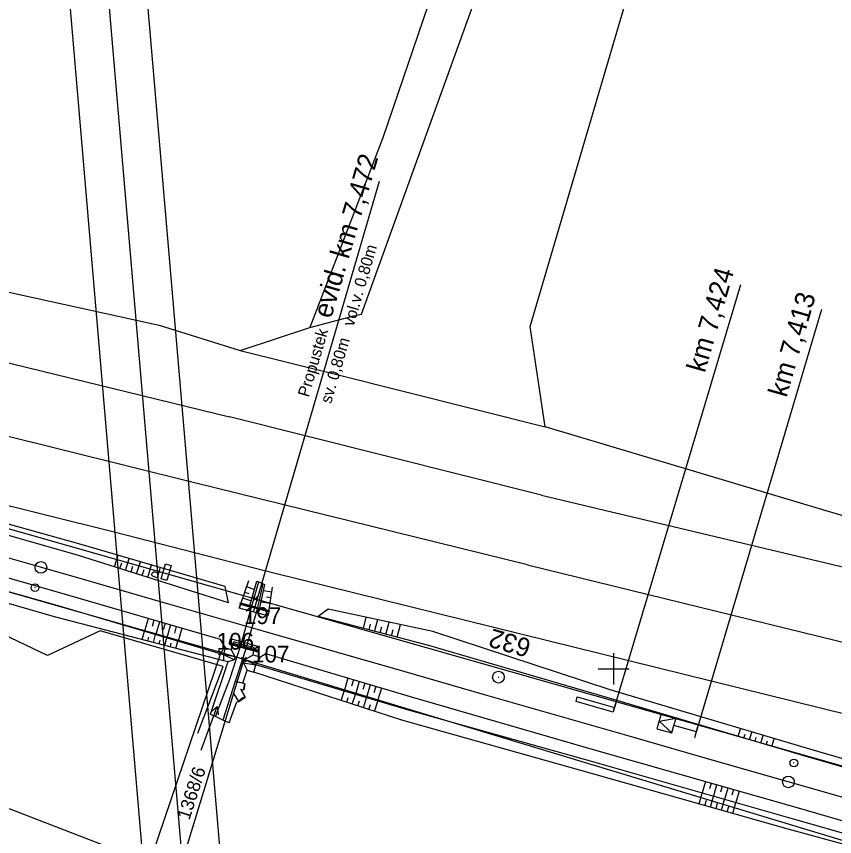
# Model space of a CAD drawing. Extents: x -779302 to -774398, y -1144902 to -1142831.
# Drawn here: x -777576.9 to -777471.5, y -1143721.6 to -1143615.9 of the extents above; entities that cross this region are included whole.
import ezdxf

# ---------------------------------------------------------------- set-up
doc = ezdxf.new("R2010")
doc.units = 0
for name, color, linetype in [('hektosit - Vrstva 5', 7, 'Continuous'), ('Hranice parcel', 7, 'Continuous'), ('legenda I_5_2 - Vrstva 53', 7, 'Continuous'), ('Parcelní čísla', 7, 'Continuous'), ('SŽDC', 7, 'Continuous'), ('Vnitřní kresba', 7, 'Continuous'), ('Vrstva 1', 7, 'Continuous'), ('zjednodus_g_situ-seda - Vrstva 1', 7, 'Continuous'), ('zjednodus_g_situ-seda - Vrstva 17', 7, 'Continuous'), ('zjednodus_g_situ-seda - Vrstva 19', 7, 'Continuous'), ('zjednodus_g_situ-seda - Vrstva 33', 7, 'Continuous'), ('zjednodus_g_situ-seda - Vrstva 48', 7, 'Continuous'), ('zjednodus_g_situ-seda - Vrstva 49', 7, 'Continuous'), ('zjednodus_g_situ-seda - Vrstva 63', 7, 'Continuous'), ('zjednodus_g_situ-seda - Vrstva 7', 7, 'Continuous'), ('zjednodus_g_situ-seda - Vrstva 8', 7, 'Continuous'), ('zjednodus_g_situ-seda - Vrstva 9', 7, 'Continuous'), ('Značky kultur', 7, 'Continuous')]:
    doc.layers.add(name, color=color, linetype=linetype)

msp = doc.modelspace()

# ---------------------------------------------------------------- linework, layer by layer
at = {"layer": 'hektosit - Vrstva 5'}
for p, q in [((-777500, -1143698), (-777500, -1143702)), ((-777502, -1143700), (-777498, -1143700))]:
    msp.add_line(p, q, dxfattribs=at)
at = {"layer": 'Hranice parcel'}
for p, q in [((-777548.1, -1143658.97), (-777539.12, -1143656)), ((-777550.6, -1143697.9), (-777622.38, -1143677.44)), ((-777550.6, -1143697.9), (-777559.79, -1143725)), ((-777547.63, -1143698.79), (-777556.08, -1143726.43)), ((-777547.63, -1143698.79), (-777550.6, -1143697.9))]:
    msp.add_line(p, q, dxfattribs=at)
for points in [[(-777508.79, -1143668.8), (-777510.73, -1143655.88), (-777497.53, -1143610.93), (-777481.94, -1143562.57), (-777470.6, -1143527.36), (-777466.94, -1143516.02), (-777464.9, -1143509.68)], [(-777496.86, -1143535.74), (-777517.68, -1143596.22), (-777520.04, -1143603.06), (-777529.74, -1143631.58), (-777539.12, -1143656)], [(-777539.12, -1143656), (-777533.45, -1143654.53), (-777532.48, -1143654.28), (-777515.5, -1143607.29), (-777513.98, -1143602.78), (-777492.04, -1143537.65)], [(-778102.74, -1143613.61), (-778067.87, -1143604.7), (-778036.9, -1143597.86), (-777971.64, -1143592.01), (-777964.3, -1143591.17), (-777890.59, -1143590.67), (-777860.75, -1143594.87), (-777857.58, -1143595.32), (-777803.43, -1143602.93), (-777799.69, -1143603.46), (-777791.04, -1143604.67), (-777558.56, -1143655.7), (-777548.1, -1143658.97)], [(-777375.98, -1143729.1), (-777462.56, -1143707.72), (-777543.96, -1143687.61), (-777544.8, -1143687.4), (-777564.35, -1143682.38), (-777643.12, -1143662.79), (-777672.41, -1143655.46), (-777784.28, -1143627.47), (-777786.92, -1143627.45)], [(-777548.1, -1143658.97), (-777536, -1143661.99), (-777508.79, -1143668.8)], [(-777773.53, -1143661.8), (-777723.87, -1143663.43), (-777711.36, -1143665.84), (-777650.39, -1143687.95), (-777582.96, -1143716.06), (-777559.79, -1143725)], [(-777371.14, -1143700.16), (-777375.2, -1143699.98), (-777393.58, -1143699.19), (-777466.8, -1143681.38), (-777472.61, -1143679.64), (-777508.79, -1143668.8)], [(-777600.4, -1143675.56), (-777546.18, -1143690.99), (-777447.49, -1143719.07), (-777442.54, -1143720.48)], [(-777358.14, -1143760.61), (-777362.08, -1143759.74), (-777364.95, -1143754.01), (-777547.63, -1143698.79)]]:
    msp.add_lwpolyline(points, dxfattribs=at)
at = {"layer": 'legenda I_5_2 - Vrstva 53'}
for points in [[(-777916.16, -1143663.29), (-777860.31, -1143656.58), (-777817.61, -1143650.87), (-777782.23, -1143650.25), (-777777.65, -1143650.04), (-777771.99, -1143649.79), (-777747.07, -1143649.03), (-777716.22, -1143651.23), (-777687.78, -1143654.61), (-777659.91, -1143659.97), (-777643.37, -1143663.67), (-777619.92, -1143670.03), (-777600.4, -1143675.56), (-777546.18, -1143690.99), (-777447.49, -1143719.07), (-777442.54, -1143720.48), (-777400.53, -1143733.41)], [(-777340.59, -1143770.61), (-777348.72, -1143768.82), (-777354.56, -1143760.13), (-777358.14, -1143760.61), (-777362.08, -1143759.74), (-777364.95, -1143754.01), (-777547.63, -1143698.79), (-777550.6, -1143697.9), (-777622.38, -1143677.44), (-777645.06, -1143671.66), (-777661.41, -1143667.34), (-777716.9, -1143658.83), (-777747.1, -1143656.66), (-777769.78, -1143657.38), (-777774.83, -1143658.21), (-777780.87, -1143658.4), (-777816.72, -1143661.12), (-777859.44, -1143665.66), (-777917.11, -1143671.65)]]:
    msp.add_lwpolyline(points, dxfattribs=at)
at = {"layer": 'SŽDC'}
for p, q in [((-777545.98, -1143691.19), (-777546.48, -1143690.69)), ((-777545.98, -1143690.79), (-777546.48, -1143691.29)), ((-777546.38, -1143691.19), (-777545.88, -1143690.69)), ((-777546.38, -1143690.79), (-777545.88, -1143691.29)), ((-777546.18, -1143690.99), (-777546.18, -1143690.99)), ((-777550.4, -1143698.1), (-777550.9, -1143697.6)), ((-777550.4, -1143697.7), (-777550.9, -1143698.2)), ((-777550.8, -1143698.1), (-777550.3, -1143697.6)), ((-777550.8, -1143697.7), (-777550.3, -1143698.2)), ((-777550.6, -1143697.9), (-777550.6, -1143697.9)), ((-777547.43, -1143698.99), (-777547.93, -1143698.49)), ((-777547.43, -1143698.59), (-777547.93, -1143699.09)), ((-777547.83, -1143698.99), (-777547.33, -1143698.49)), ((-777547.83, -1143698.59), (-777547.33, -1143699.09)), ((-777547.63, -1143698.79), (-777547.63, -1143698.79))]:
    msp.add_line(p, q, dxfattribs=at)
for points in [[(-777916.16, -1143663.29), (-777860.31, -1143656.58), (-777817.61, -1143650.87), (-777782.23, -1143650.25), (-777777.65, -1143650.04), (-777771.99, -1143649.79), (-777747.07, -1143649.03), (-777716.22, -1143651.23), (-777687.78, -1143654.61), (-777659.91, -1143659.97), (-777643.37, -1143663.67), (-777619.92, -1143670.03), (-777600.4, -1143675.56), (-777546.18, -1143690.99), (-777447.49, -1143719.07), (-777442.54, -1143720.48), (-777400.53, -1143733.41)], [(-777340.59, -1143770.61), (-777348.72, -1143768.82), (-777354.56, -1143760.13), (-777358.14, -1143760.61), (-777362.08, -1143759.74), (-777364.95, -1143754.01), (-777547.63, -1143698.79), (-777550.6, -1143697.9), (-777622.38, -1143677.44), (-777645.06, -1143671.66), (-777661.41, -1143667.34), (-777716.9, -1143658.83), (-777747.1, -1143656.66), (-777769.78, -1143657.38), (-777774.83, -1143658.21), (-777780.87, -1143658.4), (-777816.72, -1143661.12), (-777859.44, -1143665.66), (-777917.11, -1143671.65)]]:
    msp.add_lwpolyline(points, dxfattribs=at)
at = {"layer": 'Vnitřní kresba'}
for p, q in [((-777664.65, -1143639.46), (-777549.5, -1143667.53)), ((-777554.18, -1143676), (-777668.6, -1143647.45)), ((-777509.28, -1143677.62), (-777549.5, -1143667.53)), ((-777511.09, -1143686.61), (-777554.18, -1143676)), ((-777509.28, -1143677.62), (-777391.49, -1143705.71)), ((-777511.09, -1143686.61), (-777400.48, -1143713.69))]:
    msp.add_line(p, q, dxfattribs=at)
at = {"layer": 'Vrstva 1'}
for points in [[(-777571, -1143485.76), (-778617.18, -1143575.21), (-778591.88, -1143871.12), (-777545.7, -1143781.67)], [(-777551.11, -1143777.12), (-778587.32, -1143865.71), (-778611.77, -1143579.77), (-777575.56, -1143491.17)], [(-777580.11, -1143496.57), (-778407.09, -1143567.28), (-778383.5, -1143843.27), (-777556.51, -1143772.57)]]:
    msp.add_lwpolyline(points, close=True, dxfattribs=at)
at = {"layer": 'zjednodus_g_situ-seda - Vrstva 1'}
msp.add_lwpolyline([(-777408.97, -1143734.24), (-777420.06, -1143731.06), (-777430.69, -1143728), (-777441.98, -1143724.76), (-777451.96, -1143721.89), (-777462.83, -1143718.78), (-777473.72, -1143715.65), (-777477.48, -1143714.57), (-777487.28, -1143711.76), (-777497.37, -1143708.86), (-777507.6, -1143705.92), (-777516.61, -1143703.33), (-777526.83, -1143700.4), (-777537.5, -1143697.33), (-777545.14, -1143695.15), (-777548.77, -1143694.1), (-777557.76, -1143691.53), (-777568.3, -1143688.5), (-777573.86, -1143686.91), (-777584.11, -1143683.97)], dxfattribs=at)
at = {"layer": 'zjednodus_g_situ-seda - Vrstva 17'}
for p, q in [((-777544.39, -1143692.58), (-777548.07, -1143691.58)), ((-777545.82, -1143697.74), (-777549.51, -1143696.75))]:
    msp.add_line(p, q, dxfattribs=at)
msp.add_lwpolyline([(-777553.57, -1143708.27), (-777550.29, -1143699.69), (-777566.17, -1143695.1), (-777572.92, -1143698.27), (-777586.19, -1143691.95), (-777600.66, -1143686.16), (-777614.28, -1143682.28), (-777621.4, -1143682.89)], dxfattribs=at)
at = {"layer": 'zjednodus_g_situ-seda - Vrstva 19'}
for p, q in [((-777546.39, -1143692.68), (-777530.17, -1143637.17)), ((-777546.89, -1143691.99), (-777545.95, -1143688.7)), ((-777546.66, -1143692.05), (-777545.71, -1143688.79)), ((-777545.88, -1143692.25), (-777545.16, -1143689.04)), ((-777545.6, -1143692.33), (-777544.92, -1143689.12)), ((-777548.05, -1143691.51), (-777544.37, -1143692.52)), ((-777544.41, -1143692.65), (-777548.1, -1143691.67)), ((-777548, -1143696.82), (-777546.66, -1143692.05)), ((-777548, -1143696.82), (-777546.65, -1143692.05)), ((-777547.26, -1143697.02), (-777545.88, -1143692.26)), ((-777547.25, -1143697.02), (-777545.88, -1143692.25)), ((-777545.78, -1143697.62), (-777549.48, -1143696.61)), ((-777545.65, -1143697.15), (-777549.36, -1143696.15)), ((-777549.28, -1143697.49), (-777548.99, -1143696.75)), ((-777548.99, -1143696.75), (-777546.35, -1143697.47)), ((-777548, -1143696.82), (-777548.94, -1143696.52)), ((-777549.5, -1143696.82), (-777545.84, -1143697.81)), ((-777548.76, -1143698.45), (-777549.28, -1143697.49)), ((-777546.3, -1143697.27), (-777547.26, -1143697.02)), ((-777546.44, -1143698.25), (-777546.35, -1143697.47)), ((-777546.35, -1143697.47), (-777546.3, -1143697.27)), ((-777545.79, -1143697.62), (-777546.35, -1143697.47)), ((-777548.76, -1143698.45), (-777550.2, -1143698.19)), ((-777548.89, -1143698.83), (-777550.2, -1143698.19)), ((-777548.89, -1143698.83), (-777549.7, -1143699.1)), ((-777548.76, -1143698.45), (-777548.89, -1143698.83)), ((-777547.5, -1143698.79), (-777547.7, -1143699.24)), ((-777546.44, -1143698.25), (-777547.5, -1143698.79)), ((-777547.5, -1143698.79), (-777546.08, -1143699.47)), ((-777545.51, -1143698.5), (-777546.44, -1143698.25)), ((-777549.7, -1143699.1), (-777551.99, -1143705.87)), ((-777547.7, -1143699.24), (-777547.22, -1143700.18)), ((-777547.7, -1143699.24), (-777546.08, -1143699.47)), ((-777547.49, -1143701.91), (-777548.76, -1143701.61)), ((-777547.76, -1143701.86), (-777548.76, -1143701.61)), ((-777547.49, -1143701.91), (-777547.76, -1143701.86)), ((-777547.49, -1143701.91), (-777547.64, -1143702.7)), ((-777547.63, -1143702.7), (-777547.49, -1143701.91)), ((-777547.49, -1143701.91), (-777547.49, -1143701.91)), ((-777548.29, -1143704.2), (-777548.95, -1143703.09)), ((-777548.28, -1143704.2), (-777548.95, -1143703.09)), ((-777547.47, -1143703.65), (-777548.03, -1143702.62)), ((-777548.03, -1143702.62), (-777547.64, -1143702.7)), ((-777548.03, -1143702.62), (-777547.63, -1143702.7)), ((-777547.64, -1143702.7), (-777547.63, -1143702.7)), ((-777548.52, -1143704.23), (-777548.29, -1143704.2)), ((-777549.51, -1143706.95), (-777548.52, -1143704.23)), ((-777551.27, -1143706.14), (-777551.99, -1143705.87)), ((-777549.51, -1143706.95), (-777550.36, -1143706.63))]:
    msp.add_line(p, q, dxfattribs=at)
for points in [[(-777545.95, -1143688.7), (-777545.71, -1143688.79), (-777545.16, -1143689.04), (-777544.92, -1143689.12)], [(-777548.04, -1143691.52), (-777548.05, -1143691.51), (-777548.1, -1143691.67), (-777548.09, -1143691.67), (-777548.22, -1143692.18)], [(-777548.22, -1143692.18), (-777548.04, -1143691.52)], [(-777544.56, -1143693.18), (-777544.37, -1143692.52), (-777548.04, -1143691.52)], [(-777544.56, -1143693.18), (-777548.22, -1143692.18)], [(-777544.41, -1143692.65), (-777545.6, -1143692.33), (-777545.88, -1143692.25), (-777545.88, -1143692.26), (-777546.65, -1143692.05), (-777546.66, -1143692.05), (-777546.89, -1143691.99), (-777548.09, -1143691.67)], [(-777544.37, -1143692.52), (-777544.37, -1143692.52), (-777544.41, -1143692.65), (-777544.41, -1143692.65), (-777544.56, -1143693.18)], [(-777545.65, -1143697.15), (-777545.83, -1143697.81), (-777549.5, -1143696.82), (-777549.36, -1143696.15)], [(-777549.5, -1143696.82), (-777549.5, -1143696.82), (-777549.48, -1143696.61), (-777549.47, -1143696.61), (-777549.36, -1143696.15)], [(-777549.47, -1143696.61), (-777548.99, -1143696.75), (-777548.94, -1143696.52)], [(-777546.3, -1143697.27), (-777547.25, -1143697.02), (-777547.26, -1143697.02), (-777548, -1143696.82), (-777548, -1143696.82), (-777548.94, -1143696.52)], [(-777550.36, -1143706.63), (-777551.27, -1143706.14), (-777549.43, -1143701.35), (-777548, -1143696.82)], [(-777547.25, -1143697.02), (-777548.76, -1143701.61), (-777550.36, -1143706.63)], [(-777549.7, -1143699.1), (-777550.2, -1143698.98), (-777550.2, -1143698.19), (-777550.01, -1143697.31), (-777549.28, -1143697.49)], [(-777545.83, -1143697.81), (-777545.84, -1143697.81), (-777545.78, -1143697.62), (-777545.79, -1143697.62), (-777545.65, -1143697.15)], [(-777546.36, -1143700.42), (-777546.08, -1143699.47), (-777545.51, -1143698.5)], [(-777547.76, -1143701.86), (-777547.22, -1143700.18), (-777546.36, -1143700.42)], [(-777548.03, -1143702.62), (-777548.03, -1143702.62), (-777547.47, -1143703.65)], [(-777548.29, -1143704.2), (-777548.28, -1143704.2), (-777547.47, -1143703.65), (-777547.47, -1143703.65), (-777548.29, -1143704.2)]]:
    msp.add_lwpolyline(points, dxfattribs=at)
for centre, major_axis, ratio, start_param, end_param in [((-777547.59, -1143702.31), (-0.048, -0.25), 0.006452, 6.263484, 10.990254), ((-777547.59, -1143702.31), (-0.048, -0.25), 0.006452, 4.707068, 7.833837), ((-777547.97, -1143703.87), (0.234, 0.197), 0.005166, 1.392493, 4.908137), ((-777547.97, -1143703.87), (0.234, 0.197), 0.005166, 4.908137, 9.235346)]:
    msp.add_ellipse(centre, major_axis=major_axis, ratio=ratio, start_param=start_param, end_param=end_param, dxfattribs=at)
at = {"layer": 'zjednodus_g_situ-seda - Vrstva 33'}
msp.add_line((-777544.3, -1143692.6), (-777548.16, -1143691.52), dxfattribs=at)
msp.add_lwpolyline([(-777558.45, -1143687.05), (-777558.79, -1143688.26), (-777559.29, -1143688.11), (-777559.43, -1143688.02), (-777559.48, -1143687.79), (-777559.45, -1143687.69), (-777559.29, -1143687.52), (-777559.12, -1143687.52), (-777558.62, -1143687.66)], dxfattribs=at)
msp.add_lwpolyline([(-777557.57, -1143688.6), (-777558.29, -1143688.4), (-777557.73, -1143686.46), (-777557.02, -1143686.67)], close=True, dxfattribs=at)
at = {"layer": 'zjednodus_g_situ-seda - Vrstva 48'}
for p, q in [((-777564.32, -1143686.86), (-777563.85, -1143685.36)), ((-777562.89, -1143687.31), (-777562.41, -1143685.78)), ((-777561.46, -1143687.76), (-777560.97, -1143686.2)), ((-777563.6, -1143687.08), (-777563.37, -1143686.33)), ((-777562.17, -1143687.53), (-777561.93, -1143686.76)), ((-777560.74, -1143687.98), (-777560.49, -1143687.2)), ((-777560.03, -1143688.21), (-777559.53, -1143686.62)), ((-777547.3, -1143689.41), (-777546.26, -1143689.78)), ((-777547.55, -1143690.12), (-777547.01, -1143690.31)), ((-777544.05, -1143690.11), (-777545.1, -1143689.96)), ((-777547.8, -1143690.83), (-777546.67, -1143691.22)), ((-777544.26, -1143691.59), (-777545.41, -1143691.43)), ((-777544.16, -1143690.85), (-777544.7, -1143690.77)), ((-777559.95, -1143693.51), (-777560.43, -1143695.16)), ((-777532.24, -1143694.79), (-777531.86, -1143693.34)), ((-777559.23, -1143693.72), (-777559.47, -1143694.55)), ((-777558.51, -1143693.93), (-777558.99, -1143695.59)), ((-777557.79, -1143694.14), (-777558.03, -1143694.97)), ((-777557.07, -1143694.35), (-777557.56, -1143696.01)), ((-777556.35, -1143694.56), (-777556.59, -1143695.4)), ((-777531.51, -1143694.98), (-777531.32, -1143694.24)), ((-777530.79, -1143695.18), (-777530.39, -1143693.66)), ((-777530.06, -1143695.37), (-777529.86, -1143694.59)), ((-777529.34, -1143695.56), (-777528.92, -1143693.97)), ((-777527.89, -1143695.94), (-777527.45, -1143694.29)), ((-777560.74, -1143696.24), (-777560.46, -1143695.16)), ((-777559.29, -1143696.62), (-777559.02, -1143695.58)), ((-777555.63, -1143694.78), (-777556.12, -1143696.44)), ((-777528.61, -1143695.75), (-777528.4, -1143694.94)), ((-777560.02, -1143696.43), (-777559.88, -1143695.9)), ((-777558.56, -1143696.8), (-777558.43, -1143696.3)), ((-777557.84, -1143696.99), (-777557.58, -1143696.01)), ((-777557.11, -1143697.18), (-777556.99, -1143696.7)), ((-777556.39, -1143697.37), (-777556.14, -1143696.43)), ((-777534.22, -1143701.21), (-777534.71, -1143702.86)), ((-777533.5, -1143701.43), (-777533.75, -1143702.25)), ((-777532.78, -1143701.64), (-777533.27, -1143703.29)), ((-777532.06, -1143701.86), (-777532.31, -1143702.68)), ((-777531.35, -1143702.07), (-777531.84, -1143703.71)), ((-777535.1, -1143704.08), (-777534.7, -1143702.86)), ((-777530.63, -1143702.28), (-777530.87, -1143703.11)), ((-777529.91, -1143702.5), (-777530.4, -1143704.14)), ((-777534.38, -1143704.32), (-777534.18, -1143703.7)), ((-777533.67, -1143704.55), (-777533.26, -1143703.29)), ((-777532.96, -1143704.78), (-777532.75, -1143704.14)), ((-777532.24, -1143705.01), (-777531.82, -1143703.72)), ((-777530.82, -1143705.48), (-777530.38, -1143704.15)), ((-777531.53, -1143705.25), (-777531.32, -1143704.59)), ((-777483.92, -1143708.71), (-777483.62, -1143707.72)), ((-777483.2, -1143708.93), (-777483.05, -1143708.43)), ((-777482.48, -1143709.14), (-777482.18, -1143708.14)), ((-777481.76, -1143709.35), (-777481.61, -1143708.85)), ((-777481.04, -1143709.57), (-777480.74, -1143708.57)), ((-777480.32, -1143709.78), (-777480.18, -1143709.28)), ((-777479.6, -1143709.99), (-777479.31, -1143709)), ((-777488.16, -1143714.53), (-777488.58, -1143715.99)), ((-777487.44, -1143714.74), (-777487.65, -1143715.47)), ((-777486.72, -1143714.95), (-777487.14, -1143716.41)), ((-777486, -1143715.15), (-777486.21, -1143715.88)), ((-777485.28, -1143715.36), (-777485.69, -1143716.82)), ((-777484.56, -1143715.56), (-777484.76, -1143716.29)), ((-777483.83, -1143715.77), (-777484.25, -1143717.23)), ((-777488.96, -1143717.41), (-777488.56, -1143716)), ((-777487.52, -1143717.82), (-777487.12, -1143716.41)), ((-777486.07, -1143718.23), (-777485.68, -1143716.82)), ((-777488.24, -1143717.61), (-777488.04, -1143716.91)), ((-777486.79, -1143718.02), (-777486.6, -1143717.32)), ((-777485.35, -1143718.43), (-777485.15, -1143717.73)), ((-777484.63, -1143718.63), (-777484.23, -1143717.24))]:
    msp.add_line(p, q, dxfattribs=at)
at = {"layer": 'zjednodus_g_situ-seda - Vrstva 49'}
for p, q in [((-777547.03, -1143688.64), (-777548.09, -1143691.67)), ((-777544.41, -1143692.65), (-777543.96, -1143689.47))]:
    msp.add_line(p, q, dxfattribs=at)
for points in [[(-777549.6, -1143691.48), (-777550.06, -1143689.38), (-777568.6, -1143683.97), (-777593.4, -1143677.06), (-777596.41, -1143676.2), (-777599.98, -1143675.75), (-777619.03, -1143670.64), (-777644.91, -1143663.71), (-777675.1, -1143657.41), (-777705.47, -1143653.06), (-777734.69, -1143650.26), (-777752.7, -1143649.71)], [(-777550.2, -1143698.98), (-777550.2, -1143698.19), (-777550.01, -1143697.31), (-777550.64, -1143696.23), (-777570.3, -1143690.49), (-777595.3, -1143683.34), (-777620.52, -1143676.17), (-777634.34, -1143672.19), (-777646.38, -1143669.03), (-777660.8, -1143665.62), (-777676.03, -1143662.72), (-777690.25, -1143660.18), (-777706.04, -1143658.02), (-777720.74, -1143656.51), (-777735.02, -1143655.6), (-777749.52, -1143654.84), (-777764, -1143654.74), (-777775.16, -1143654.64), (-777774.7, -1143656.53)], [(-777550.2, -1143698.19), (-777571.58, -1143691.86), (-777595.86, -1143684.99), (-777620.66, -1143677.27), (-777646.79, -1143670.07), (-777675.98, -1143663.38), (-777706.15, -1143658.86), (-777734.95, -1143656.49), (-777764.01, -1143655.46), (-777774.57, -1143655.38)], [(-777550.2, -1143698.98), (-777572.03, -1143693.31), (-777596.56, -1143686.21), (-777621.06, -1143678.33), (-777647.2, -1143671.2), (-777676.34, -1143664.76), (-777706.24, -1143660.17), (-777735.08, -1143657.84), (-777764.06, -1143656.85), (-777774.7, -1143656.53)], [(-777549.6, -1143691.48), (-777568.95, -1143685.41), (-777594.05, -1143678.21), (-777619.09, -1143671.25), (-777633.09, -1143667.53), (-777645.08, -1143664.32), (-777659.94, -1143660.98), (-777675.1, -1143658.13)], [(-777548.09, -1143691.67), (-777546.89, -1143691.99), (-777545.95, -1143688.7)], [(-777544.41, -1143692.65), (-777545.6, -1143692.33), (-777544.92, -1143689.12)], [(-777451.84, -1143717.02), (-777474.69, -1143710.37), (-777500.45, -1143702.72), (-777523.3, -1143695.17), (-777536.76, -1143692.3), (-777538.08, -1143693.25)], [(-777450.05, -1143718.16), (-777452.08, -1143717.97), (-777474.88, -1143711.4), (-777500.86, -1143703.68), (-777523.99, -1143696.97), (-777538.08, -1143693.25)], [(-777546.36, -1143700.42), (-777546.08, -1143699.47), (-777545.51, -1143698.5)], [(-777364.74, -1143750.19), (-777380.7, -1143745.49), (-777403.78, -1143738.74), (-777428.64, -1143731.61), (-777452.79, -1143724.72), (-777476.47, -1143717.87), (-777502.28, -1143710.5), (-777526.17, -1143703.62), (-777544.81, -1143698.05), (-777545.51, -1143698.5)], [(-777364.89, -1143751.11), (-777380.8, -1143746.49), (-777403.99, -1143739.89), (-777428.76, -1143732.86), (-777453.33, -1143726.06), (-777477.09, -1143719.28), (-777502.66, -1143711.96), (-777526.41, -1143705.33), (-777546.08, -1143699.47)], [(-777365.24, -1143752.61), (-777381.35, -1143747.71), (-777404.38, -1143741.25), (-777429.09, -1143734.06), (-777453.43, -1143727.23), (-777477.49, -1143720.65), (-777502.86, -1143713.48), (-777527.3, -1143706.63), (-777546.36, -1143700.42)]]:
    msp.add_lwpolyline(points, dxfattribs=at)
at = {"layer": 'zjednodus_g_situ-seda - Vrstva 63'}
msp.add_line((-777514.88, -1143701.07), (-777514.78, -1143701.07), dxfattribs=at)
msp.add_circle((-777514.83, -1143701.07), 0.756, dxfattribs=at)
at = {"layer": 'zjednodus_g_situ-seda - Vrstva 7'}
for p, q in [((-777574.5, -1143689.55), (-777574.59, -1143689.52)), ((-777476.71, -1143712.14), (-777476.81, -1143712.11))]:
    msp.add_line(p, q, dxfattribs=at)
for centre, radius in [((-777573.79, -1143686.93), 0.75), ((-777574.55, -1143689.54), 0.5), ((-777476.76, -1143712.13), 0.5), ((-777477.47, -1143714.57), 0.75)]:
    msp.add_circle(centre, radius, dxfattribs=at)
at = {"layer": 'zjednodus_g_situ-seda - Vrstva 8'}
for p, q in [((-777489.33, -1143708.13), (-777473.18, -1143653.64)), ((-777489.54, -1143708.85), (-777489.12, -1143707.41))]:
    msp.add_line(p, q, dxfattribs=at)
for points in [[(-777489.33, -1143708.13), (-777492.21, -1143707.3), (-777491.94, -1143706.34), (-777493.86, -1143705.79), (-777494.41, -1143707.71), (-777492.49, -1143708.26), (-777492.21, -1143707.3)], [(-777492.49, -1143708.26), (-777494.14, -1143706.75), (-777491.94, -1143706.34)]]:
    msp.add_lwpolyline(points, dxfattribs=at)
at = {"layer": 'zjednodus_g_situ-seda - Vrstva 9'}
msp.add_line((-777499.95, -1143705.28), (-777483.6, -1143650.46), dxfattribs=at)
msp.add_lwpolyline([(-777499.7, -1143704.42), (-777499.86, -1143705), (-777500.03, -1143705.57), (-777504.83, -1143704.19), (-777504.67, -1143703.62), (-777499.86, -1143705)], dxfattribs=at)
at = {"layer": 'Značky kultur'}
for p, q in [((-777553.14, -1143710.48), (-777551.09, -1143704.84)), ((-777551.09, -1143704.84), (-777551.9, -1143705.58)), ((-777551.09, -1143704.84), (-777550.95, -1143705.93))]:
    msp.add_line(p, q, dxfattribs=at)

# ---------------------------------------------------------------- texts
at = {"layer": 'Parcelní čísla'}
msp.add_text('1368/6', height=1.7, rotation=72, dxfattribs=at).set_placement((-777554.66, -1143719.57))
at = {"layer": 'SŽDC'}
for s, p in [('197', (-777547.64, -1143694.23)), ('106', (-777551.14, -1143697.53)), ('107', (-777546.58, -1143699.18))]:
    msp.add_text(s, height=2.16, dxfattribs=at).set_placement(p)
at = {"layer": 'zjednodus_g_situ-seda - Vrstva 19'}
for s, height, p in [('evid. km 7,472', 2.5, (-777536.39, -1143654.97)), ('sv. 0,80m   vol.v. 0,80m', 1.5, (-777536.4, -1143665.92)), ('Propustek', 1.5, (-777539.28, -1143665.08))]:
    msp.add_text(s, height=height, rotation=73.7123, dxfattribs=at).set_placement(p)
at = {"layer": 'zjednodus_g_situ-seda - Vrstva 63'}
msp.add_text('632', height=2.4, rotation=163.9664, dxfattribs=at).set_placement((-777510.47, -1143696.27))
at = {"layer": 'zjednodus_g_situ-seda - Vrstva 8'}
msp.add_text('km 7,413', height=2.5, rotation=73.9864, dxfattribs=at).set_placement((-777477.71, -1143665.13))
at = {"layer": 'zjednodus_g_situ-seda - Vrstva 9'}
msp.add_text('km 7,424', height=2.5, rotation=73.9822, dxfattribs=at).set_placement((-777488.24, -1143661.95))

doc.saveas('drawing.dxf')
